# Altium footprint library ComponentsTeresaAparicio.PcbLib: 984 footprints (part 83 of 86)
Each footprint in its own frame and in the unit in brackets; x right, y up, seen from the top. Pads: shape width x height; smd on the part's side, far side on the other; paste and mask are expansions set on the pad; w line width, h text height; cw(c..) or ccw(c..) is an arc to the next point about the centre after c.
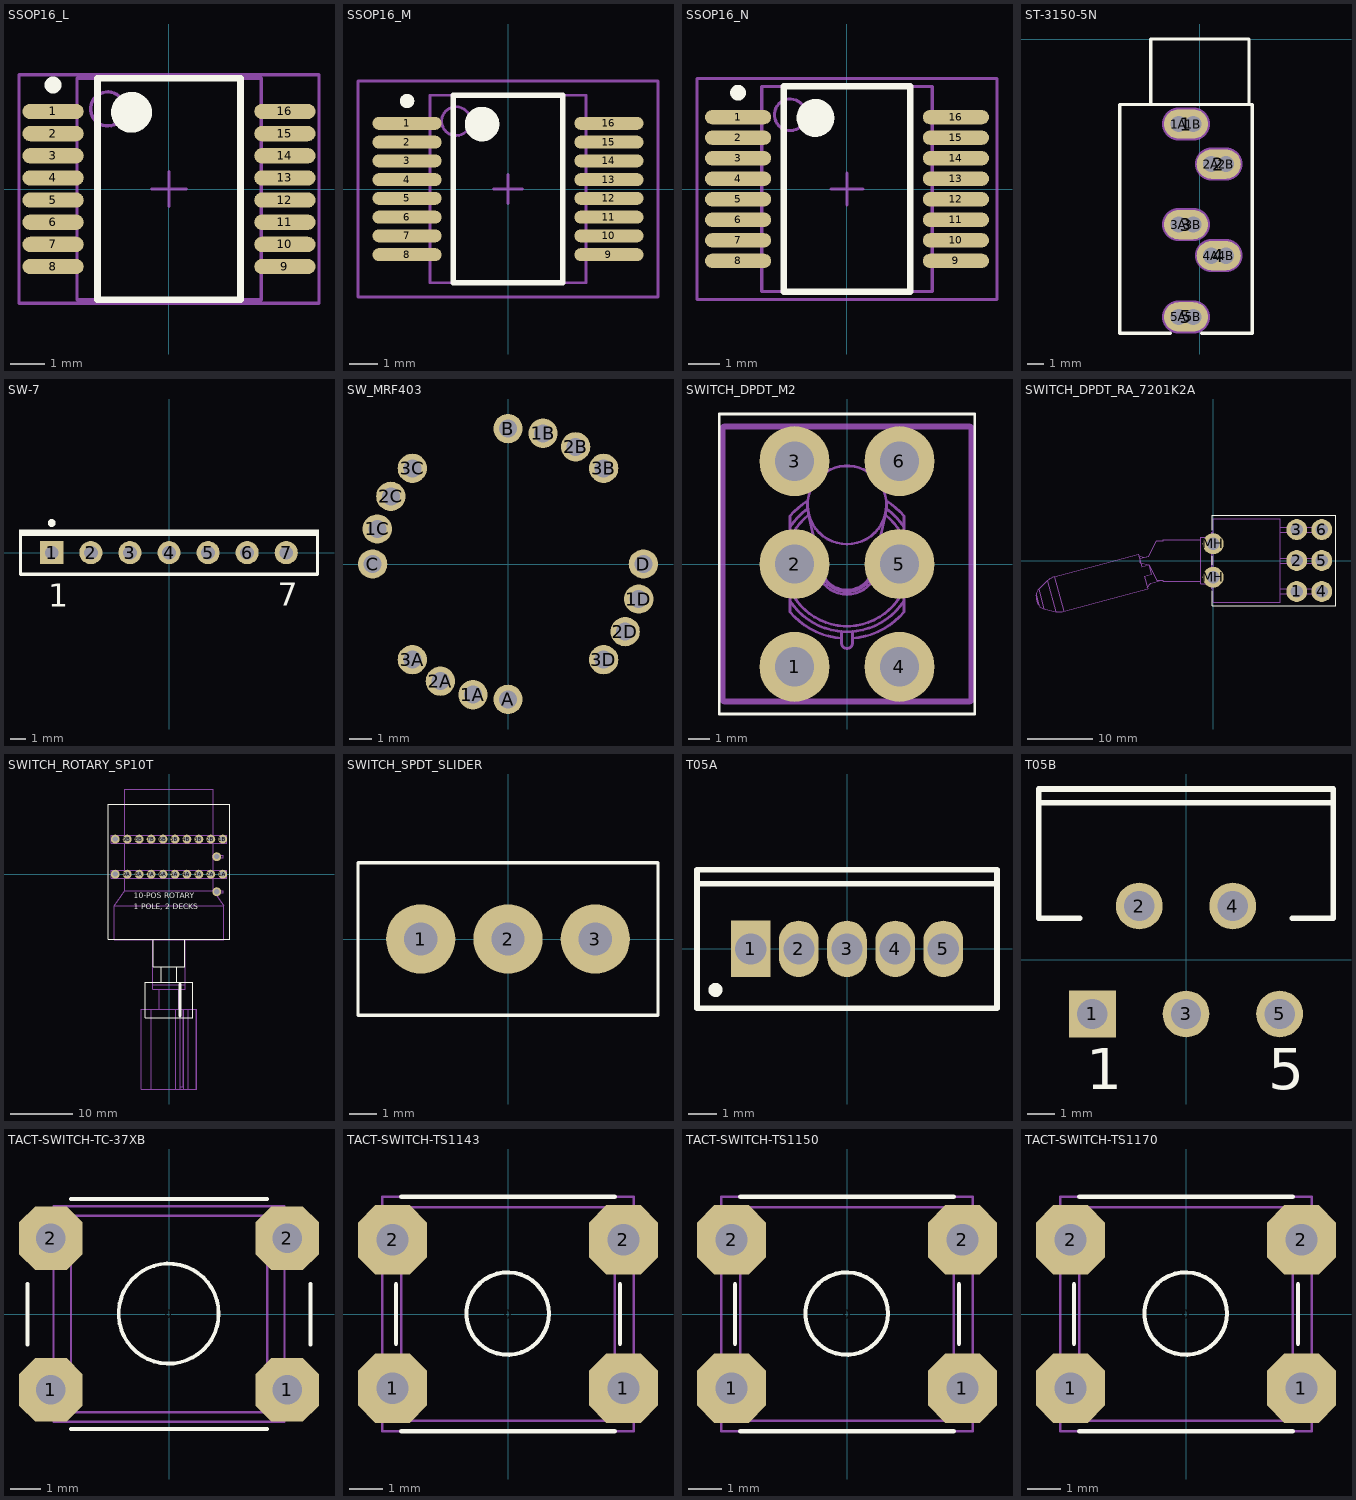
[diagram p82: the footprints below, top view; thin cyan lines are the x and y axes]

## SSOP16_L [mm] "SOP, 16-Leads, Body 6.2x5.3mm, Pitch 0.65mm, IPC High Density"
height 2
pads (16):
  oval 1.8x0.45 smd: 1(-3.4,2.275) 2(-3.4,1.625) 3(-3.4,0.975) 4(-3.4,0.325) 5(-3.4,-0.325) 6(-3.4,-0.975) 7(-3.4,-1.625) 8(-3.4,-2.275) 9(3.4,-2.275) 10(3.4,-1.625) 11(3.4,-0.975) 12(3.4,-0.325) 13(3.4,0.325) 14(3.4,0.975) 15(3.4,1.625) 16(3.4,2.275)
Top Overlay:
  circle w0.6: c-1.1,2.25 r0.3
  circle w0.25: c-3.4,3.05 r0.125
  lines w0.2: -2.1,-3.25 2.1,-3.25 2.1,3.25 -2.1,3.25 -2.1,-3.25
Mechanical 13:
  circle w0.1: c-1.8,2.35 r0.5
  lines w0.1: -2.7,-3.25 2.7,-3.25 2.7,3.25 -2.7,3.25 -2.7,-3.25
Mechanical 15:
  lines w0.1: -0.5,0 0.5,0 ; 0,-0.5 0,0.5 ; -4.4,-3.35 4.4,-3.35 4.4,3.35 -4.4,3.35 -4.4,-3.35
3D body: height 2, standoff 0, extent -2.7,-3.25 2.7,3.25

## SSOP16_M [mm] "SOP, 16-Leads, Body 6.2x5.3mm, Pitch 0.65mm, IPC Low Density"
height 2
pads (16):
  oval 2.4x0.45 smd: 1(-3.5,2.275) 2(-3.5,1.625) 3(-3.5,0.975) 4(-3.5,0.325) 5(-3.5,-0.325) 6(-3.5,-0.975) 7(-3.5,-1.625) 8(-3.5,-2.275) 9(3.5,-2.275) 10(3.5,-1.625) 11(3.5,-0.975) 12(3.5,-0.325) 13(3.5,0.325) 14(3.5,0.975) 15(3.5,1.625) 16(3.5,2.275)
Top Overlay:
  circle w0.6: c-0.9,2.25 r0.3
  circle w0.25: c-3.5,3.05 r0.125
  lines w0.2: -1.9,-3.25 1.9,-3.25 1.9,3.25 -1.9,3.25 -1.9,-3.25
Mechanical 13:
  circle w0.1: c-1.8,2.35 r0.5
  lines w0.1: -2.7,-3.25 2.7,-3.25 2.7,3.25 -2.7,3.25 -2.7,-3.25
Mechanical 15:
  lines w0.1: -0.5,0 0.5,0 ; 0,-0.5 0,0.5 ; -5.2,-3.75 5.2,-3.75 5.2,3.75 -5.2,3.75 -5.2,-3.75
3D body: height 2, standoff 0, extent -2.7,-3.25 2.7,3.25

## SSOP16_N [mm] "SOP, 16-Leads, Body 6.2x5.3mm, Pitch 0.65mm, IPC Medium Density"
height 2
pads (16):
  oval 2.1x0.45 smd: 1(-3.45,2.275) 2(-3.45,1.625) 3(-3.45,0.975) 4(-3.45,0.325) 5(-3.45,-0.325) 6(-3.45,-0.975) 7(-3.45,-1.625) 8(-3.45,-2.275) 9(3.45,-2.275) 10(3.45,-1.625) 11(3.45,-0.975) 12(3.45,-0.325) 13(3.45,0.325) 14(3.45,0.975) 15(3.45,1.625) 16(3.45,2.275)
Top Overlay:
  circle w0.6: c-1,2.25 r0.3
  circle w0.25: c-3.45,3.05 r0.125
  lines w0.2: -2,-3.25 2,-3.25 2,3.25 -2,3.25 -2,-3.25
Mechanical 13:
  circle w0.1: c-1.8,2.35 r0.5
  lines w0.1: -2.7,-3.25 2.7,-3.25 2.7,3.25 -2.7,3.25 -2.7,-3.25
Mechanical 15:
  lines w0.1: -0.5,0 0.5,0 ; 0,-0.5 0,0.5 ; -4.75,-3.5 4.75,-3.5 4.75,3.5 -4.75,3.5 -4.75,-3.5
3D body: height 2, standoff 0, extent -2.7,-3.25 2.7,3.25

## ST-3150-5N [mm] "Connector; Stereo Jack, 3.5mm, 5 Position"
pads (15):
  oval 2.7x1.8 all layers, no hole: 1(-0.85,-5.2) 2(1.15,-7.65) 3(-0.85,-11.35) 4(1.15,-13.25) 5(-0.85,-17)
  round 1.2 hole 1: 1A(-1.3,-5.2) 1B(-0.4,-5.2) 2A(0.7,-7.65) 2B(1.6,-7.65) 3A(-1.3,-11.35) 3B(-0.4,-11.35) 4A(0.7,-13.25) 4B(1.6,-13.25) 5A(-1.3,-17) 5B(-0.4,-17)
Top Overlay:
  lines w0.2: -3,-4 -3,0 3,0 3,-4 ; -1.8,-18 -4.9,-18 -4.9,-4 3.2,-4 3.2,-18 0.1,-18
Mechanical 1:
  lines w1: -1.3,-17 -0.4,-17 ; -1.3,-11.35 -0.4,-11.35 ; -1.3,-5.2 -0.4,-5.2 ; 0.7,-13.25 1.6,-13.25 ; 0.7,-7.65 1.6,-7.65
  text "Alert PCB fab to slot details" at -7.226,1.874 h0.3
  text "Slot 1x1.9mm, PTH" at -7.226,1.374 h0.3
  text "Assign keep-out area to slot" at -7.226,2.374 h0.3
  text "Mech 1 - Slot cut-out" at -7.226,0.874 h0.3
  text "Mech 2 - Clearance, move to internal plane if present" at -7.226,0.374 h0.3
Mechanical 2:
  lines w2.016: -1.3,-17 -0.4,-17 ; -1.3,-11.35 -0.4,-11.35 ; -1.3,-5.2 -0.4,-5.2 ; 0.7,-13.25 1.6,-13.25 ; 0.7,-7.65 1.6,-7.65

## SW-7 [mm] "Switch; 7 Leads"
pads (7):
  rect 1.5x1.5 hole 0.9: 1(-7.62,0)
  round 1.5 hole 0.9: 2(-5.08,0) 3(-2.54,0) 4(0,0) 5(2.54,0) 6(5.08,0) 7(7.62,0)
Top Overlay:
  circle w0.25: c-7.625,1.929 r0.125
  rectangle: -9.75,1.1 9.75,1.5
  lines w0.2: -9.65,1.4 -9.65,-1.4 9.65,-1.4 9.65,1.4
  text "1" at -7.851,-3.526 h1.5
  text "7" at 7.084,-3.445 h1.5

## SW_MRF403 [mm]
height 8.2
pads (16):
  round 1.3 hole 0.8: 1A(-1.553,-5.796) 1B(1.553,5.796) 1C(-5.796,1.553) 1D(5.796,-1.553) 2A(-3,-5.196) 2B(3,5.196) 2C(-5.196,3) 2D(5.196,-3) 3A(-4.243,-4.243) 3B(4.243,4.243) 3C(-4.243,4.243) 3D(4.243,-4.243) A(0,-6) B(0,6) C(-6,0) D(6,0)
3D body: height 8.2, standoff -3.51, extent -9.896,-9.896 9.896,9.896

## SWITCH_DPDT_M2 [mm] "NKK M2 Series DPDT Switch with 03 pin option"
height 28.448
pads (6):
  round 3.2 hole 1.8: 1(-2.4,-4.7) 2(-2.4,0) 3(-2.4,4.7) 4(2.4,-4.7) 5(2.4,0) 6(2.4,4.7)
Top Overlay:
  lines w0.127: -5.842,-6.858 5.842,-6.858 5.842,6.858 -5.842,6.858 -5.842,-6.858
Mechanical 13:
  lines w0.127: -5.716,-6.313 -5.626,-6.223 ; -5.716,6.313 -5.626,6.223 ; -2.604,-1.681 ccw(c0,0) 2.604,-1.681 ; -2.604,-1.147 ccw(c0,0) 2.604,-1.147 ; -2.604,1.147 cw(c0,0) -1.752,2.241 ; -2.604,1.681 cw(c0,0) -1.801,2.522 ; -1.795,2.892 ccw(c0,0) -2.604,2.192 -2.604,-2.192 ccw(c0,0) -0.254,-3.394 ; -1.766,2.302 -1.191,-0.254 ccw(c0,0.033) 1.191,-0.254 1.766,2.302 ; -1.338,0.401 ccw(c0,0) 1.338,0.401 ; -1.267,0.085 ccw(c0,0) 1.267,0.085 ; -0.254,-3.088 -0.254,-3.607 ccw(c0,-3.607) 0.254,-3.607 0.254,-3.088 ; 0.254,-3.394 ccw(c0,0) 2.604,-2.192 2.604,2.192 ccw(c0,0) 1.795,2.892 ; 1.752,2.241 cw(c0,0) 2.604,1.147 ; 1.801,2.522 cw(c0,0) 2.604,1.681 ; 5.716,-6.313 5.626,-6.223 ; 5.716,6.313 5.626,6.223 ; -5.626,-6.223 -5.626,6.223 ; -5.626,-6.223 5.626,-6.223 ; -5.626,6.223 5.626,6.223 ; 5.626,-6.223 5.626,6.223 ; -5.753,-6.223 ccw(c-5.626,-6.223) -5.626,-6.35 5.626,-6.35 ccw(c5.626,-6.223) 5.753,-6.223 5.753,6.223 ccw(c5.626,6.223) 5.626,6.35 -5.626,6.35 ccw(c-5.626,6.223) -5.753,6.223 -5.753,-6.223 ; -1.808,2.679 ccw(c0,2.715) 1.808,2.679 ccw(c0,2.679) -1.808,2.679
3D body: height 29.15, standoff -4.8, extent -5.753,-6.35 5.753,6.35

## SWITCH_DPDT_RA_7201K2A [mil] "DPDT Switch Right-angle PCB mount - C&K 7201K2A"
height 450
pads (8):
  round 125 hole 73: 1(500,-185) 2(500,0) 3(500,185) 4(650,-185) 5(650,0) 6(650,185) MH(0,-100) MH(0,100)
Top Overlay:
  lines w5: -5,-180 -5,-270 735,-270 735,270 -5,270 -5,180 ; -5,-25 -5,25
Mechanical 13:
  lines w1.97: -445.94,27.92 -415.18,18.2 -384.21,26.59 ; -395.27,-159.34 -373.61,-135.45 -309.44,-118.08 ; -75,-125 -298.04,-125 -298.04,-118.08 -338.46,-118.08 -385,-25 ; -75,125 -298.04,125 -298.04,118.08 -338.46,118.08 -385,25 -435,12.5 -435,-12.5 -385,-25 ; -10,-145 0,-145 ; -10,-140 -75,-140 -75,140 -10,140 ; -10,145 0,145 ; 0,-170 -10,-170 -10,170 0,170 ; 400,-200 675,-200 675,-170 400,-170 ; 400,-15 675,-15 675,15 400,15 ; 400,170 675,170 675,200 400,200 ; 610,-200 610,-170 ; 610,-15 610,15 ; 610,170 610,200 ; -1060.2,-211.44 ccw(c-960.2,-211.71) -1046.43,-262.36 ; -1060.2,-211.44 -1046.43,-262.36 ; -1060.2,-211.44 -1060.19,-208.22 ; -1060.19,-208.22 cw(c-1010.19,-208.35) -1044.77,-172.23 ; -1060.19,-208.22 -1044.79,-265.13 ; -1046.43,-262.36 -1044.79,-265.13 ; -1044.79,-265.13 ccw(c-1001.68,-239.81) -1013.33,-288.43 ; -1044.77,-172.24 -1013.33,-288.43 ; -1044.77,-172.24 -992.57,-122.27 ; -1013.33,-288.43 -943.06,-305.26 ; -992.57,-122.27 cw(c-923.42,-194.5) -949.54,-97.97 ; -992.57,-122.27 -943.06,-305.26 ; -949.54,-97.97 -893.64,-304.55 ; -949.54,-97.97 -448.55,37.57 -428.44,-36.75 -385,-25 ; -943.06,-305.26 ccw(c-919.76,-208.02) -893.64,-304.55 ; -893.64,-304.55 -392.66,-169 -412.77,-94.67 -369.33,-82.92 -385,-25 ; 0,-250 0,250 400,250 400,-250 0,-250
3D body: height 450, standoff -125, extent -1060.14,-308 675,250.01

## SWITCH_ROTARY_SP10T [mil] "Grayhill 71AF style 2-deck single pole 10-position rotary switch"
height 712.6
pads (22):
  round 56 hole 32: 1A(337.5,0) 1B(337.5,220) 2A(262.5,0) 2B(262.5,220) 3A(187.5,0) 3B(187.5,220) 4A(112.5,0) 4B(112.5,220) 5A(37.5,0) 5B(37.5,220) 6A(-37.5,0) 6B(-37.5,220) 7A(-112.5,0) 7B(-112.5,220) 8A(-187.5,0) 8B(-187.5,220) 9A(-262.5,0) 9B(-262.5,220) 10A(-337.5,0) 10B(-337.5,220) C1A(300,-110) C1B(300,110)
Top Overlay:
  lines w5: -100,-410 -100,-580 100,-580 100,-410 ; -50,-580 -50,-680 50,-680 50,-580 ; -380,-410 -380,440 380,440 380,-410 -380,-410 ; -150,-900 -150,-680 150,-680 150,-900 -150,-900
  lines w20: 70,-890 70,-690
  text "1 POLE, 2 DECKS" at -220,-220 h35
  text "10-POS ROTARY" at -220,-150 h35
Mechanical 13:
  lines w5: -343.5,-25 -343.5,25 ; -343.5,195 -343.5,245 ; -278.5,-25 -278.5,-104.17 ; -278.5,25 -278.5,195 ; -278.5,245 -278.5,535 278.5,535 278.5,245 ; -112.06,-1349 -112.06,-849 ; -101.5,-694 101.5,-694 ; -101.5,-412 -101.5,-724 101.5,-724 101.5,-412 ; -62.5,-849 -62.5,-724 ; 43.85,-1349 43.85,-849 ; 62.5,-849 62.5,-724 ; 70,-1349 70,-849 ; 70,-1334 89.14,-1334 89.14,-849 ; 93.78,-1349 93.78,-849 ; 119.93,-1349 119.93,-849 ; 169.67,-1349 169.67,-849 ; 278.5,-102.5 278.5,-25 ; 278.5,25 278.5,102.5 ; 278.5,117.5 278.5,195 ; 287.83,-117.5 343.5,-197 ; 343.5,-25 343.5,25 ; 343.5,195 343.5,245 ; -343.5,-197 -343.5,-412 343.5,-412 343.5,-197 ; -343.5,-197 -278.5,-104.17 ; -343.5,-197 343.5,-197 ; -278.5,-104.17 275.61,-104.17 ; 275.61,-104.17 285.04,-117.5 340,-117.5 340,-102.5 275.61,-102.5 275.61,-104.17 ; -362.5,-25 362.5,-25 362.5,25 -362.5,25 -362.5,-25 ; -362.5,195 362.5,195 362.5,245 -362.5,245 -362.5,195 ; -175,-1349 -175,-849 175,-849 175,-1349 -175,-1349 ; 275.61,102.5 275.61,117.5 340,117.5 340,102.5 275.61,102.5
3D body: height 711.5, standoff -156, extent -362.49,-1348.99 362.51,535

## SWITCH_SPDT_SLIDER [mil] "TE Connectivity SLS121PC04 SPDT slider"
height 396
pads (3):
  round 100 hole 48: 1(-126,0) 2(0,0) 3(126,0)
Top Overlay:
  lines w5: -216.54,-110.24 216.54,-110.24 216.54,110.24 -216.54,110.24 -216.54,-110.24
3D body: height 394, standoff -170, extent -216.49,-109.99 216.51,110.01

## T05A [mm] "TO, Thru-Hole, Vertical, Heatsink Mounted; 5 In-Line Leads; Pitch 1.70 mm"
height 15.9
pads (5):
  rect 1.4x2 hole 1.1: 1(-3.4,0)
  oval 1.4x2 hole 1.1: 2(-1.7,0) 3(0,0) 4(1.7,0) 5(3.4,0)
Top Overlay:
  circle w0.25: c-4.65,-1.45 r0.125
  lines w0.2: -5.3,2.3 5.3,2.3 ; -5.3,-2.1 5.3,-2.1 5.3,2.8 -5.3,2.8 -5.3,-2.1
Mechanical 13:
  lines w0.1: -5.3,2.3 5.3,2.3 ; -5.3,-2.1 -5.3,2.8 5.3,2.8 5.3,-2.1 -5.3,-2.1 ; -3.91,-0.28 -3.91,0.28 -2.89,0.28 -2.89,-0.28 -3.91,-0.28 ; -2.21,-0.28 -2.21,0.28 -1.19,0.28 -1.19,-0.28 -2.21,-0.28 ; -0.51,-0.28 -0.51,0.28 0.51,0.28 0.51,-0.28 -0.51,-0.28 ; 1.19,-0.28 1.19,0.28 2.21,0.28 2.21,-0.28 1.19,-0.28 ; 2.89,-0.28 2.89,0.28 3.91,0.28 3.91,-0.28 2.89,-0.28
Mechanical 15:
  lines w0.1: -0.5,0 0.5,0 ; 0,-0.5 0,0.5
3D body: height 4.1, standoff 0, extent -0.509,-0.279 0.509,0.279
3D body: height 4.1, standoff 0, extent 2.891,-0.279 3.909,0.279
3D body: height 4.1, standoff 0, extent 1.191,-0.279 2.209,0.279
3D body: height 4.1, standoff 0, extent -2.209,-0.279 -1.191,0.279
3D body: height 4.1, standoff 0, extent -3.909,-0.279 -2.891,0.279
3D body: height 13, standoff 4.1, extent -5.35,-2.15 5.35,2.85
3D body: height 15.9, standoff 13, extent -5.299,2.301 5.299,2.799

## T05B [mm] "TO, Thru-Hole, Vertical, Heatsink Mounted; 5 Bent Staggered Leads; Pitch 1.7 mm"
height 21.1
pads (5):
  rect 1.7x1.7 hole 1.1: 1(-3.4,-1.96)
  round 1.7 hole 1.1: 2(-1.7,1.96) 3(0,-1.96) 4(1.7,1.96) 5(3.4,-1.96)
Top Overlay:
  lines w0.2: -5.35,5.71 5.35,5.71 ; -3.854,1.51 -5.35,1.51 -5.35,6.21 5.35,6.21 5.35,1.51 3.854,1.51
  text "1" at -3.62,-4.685 h1.5
  text "5" at 2.98,-4.685 h1.5

## TACT-SWITCH-TC-37XB [mm] "Wealth Metal sealed TH tact switch"
height 5
pads (5):
  round 0.508 on Mech14: 0(0,0)
  oct 2.1x2.1 hole 0.965: 1(-3.9,-2.5) 1(3.9,-2.5) 2(-3.9,2.5) 2(3.9,2.5)
Top Overlay:
  circle w0.127: c-0.011,0.014 r1.65
  lines w0.127: -4.67,-1 -4.67,1 ; -3.239,-3.791 3.24,-3.791 ; -3.232,3.794 3.24,3.794 ; 4.67,-1 4.67,1
Mechanical 13:
  circle w0.076: c-0.011,0.014 r1.65
  lines w0.076: -3.232,-3.237 -3.232,3.24 3.24,3.24 3.24,-3.237 -3.232,-3.237
Mechanical 14:
  lines w0.076: -3.81,-3.556 3.81,-3.556 3.81,3.556 -3.81,3.556 -3.81,-3.556
3D body: height 5, standoff -3.9, extent -4.456,-3.6 4.456,3.6

## TACT-SWITCH-TS1143 [mm] "Bondtact sealed TH tact switch"
height 4.318
pads (5):
  round 0.508 on Mech14: 0(0,0)
  oct 2.1x2.1 hole 0.965: 1(-3.5,-2.25) 1(3.5,-2.25) 2(-3.5,2.25) 2(3.5,2.25)
Top Overlay:
  circle w0.127: c-0.011,0.014 r1.25
  lines w0.127: -3.4,-0.9 -3.4,0.9 ; -3.239,-3.556 3.24,-3.556 ; -3.236,3.556 3.236,3.556 ; 3.4,-0.9 3.4,0.9
Mechanical 13:
  circle w0.076: c-0.011,0.014 r1.25
  lines w0.076: -3.232,-3.237 3.24,-3.237 3.24,3.24 -3.232,3.24 -3.232,-3.237
Mechanical 14:
  lines w0.076: -3.81,-3.556 -3.81,3.556 3.81,3.556 3.81,-3.556 -3.81,-3.556
3D body: height 4.3, standoff -3.5, extent -4.134,-3.25 4.134,3.25

## TACT-SWITCH-TS1150 [mm] "Bondtact sealed TH tact switch"
height 5.18
pads (5):
  round 0.508 on Mech14: 0(0,0)
  oct 2.1x2.1 hole 0.965: 1(-3.5,-2.25) 1(3.5,-2.25) 2(-3.5,2.25) 2(3.5,2.25)
Top Overlay:
  circle w0.127: c-0.011,0.014 r1.25
  lines w0.127: -3.4,-0.9 -3.4,0.9 ; -3.239,-3.556 3.24,-3.556 ; -3.236,3.556 3.236,3.556 ; 3.4,-0.9 3.4,0.9
Mechanical 13:
  circle w0.076: c-0.011,0.014 r1.25
  lines w0.076: -3.232,-3.237 -3.232,3.24 3.24,3.24 3.24,-3.237 -3.232,-3.237
Mechanical 14:
  lines w0.076: -3.81,-3.556 3.81,-3.556 3.81,3.556 -3.81,3.556 -3.81,-3.556
3D body: height 5, standoff -3.5, extent -4.134,-3.25 4.134,3.25

## TACT-SWITCH-TS1170 [mm] "Bondtact sealed TH tact switch"
height 6.985
pads (5):
  round 0.508 on Mech14: 0(0,0)
  oct 2.1x2.1 hole 0.965: 1(-3.5,-2.25) 1(3.5,-2.25) 2(-3.5,2.25) 2(3.5,2.25)
Top Overlay:
  circle w0.127: c-0.011,0.014 r1.25
  lines w0.127: -3.4,-0.9 -3.4,0.9 ; -3.239,-3.556 3.24,-3.556 ; -3.236,3.556 3.236,3.556 ; 3.4,-0.9 3.4,0.9
Mechanical 13:
  circle w0.076: c-0.011,0.014 r1.25
  lines w0.076: -3.232,-3.237 -3.232,3.24 3.24,3.24 3.24,-3.237 -3.232,-3.237
Mechanical 14:
  lines w0.076: -3.81,-3.556 3.81,-3.556 3.81,3.556 -3.81,3.556 -3.81,-3.556
3D body: height 7, standoff -3.5, extent -4.134,-3.25 4.134,3.25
